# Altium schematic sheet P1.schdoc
size 660 x 381 mm; Symbol: Drawing-Symbol_A4; @Project Name: Assisant vocal; @Page Count: 1; @Update Date: 2026-05-30; @Create Date: 2026-02-09; @Schematic Name: Cerveau; @Page No: 1; @Page Name: P1; Company: EasyEDA.com; Version: V1.0; Page Size: A4; @Create Time: 11:08:47; @Update Time: 16:26:07; Border: 1; Width: 2600; Height: 1500; Region Start: 1; X Region Count: 6; Y Region Count: 4; Blade Width: 10; Title Block Position: 3; @Board Name: Cerveau; Device: Drawing-Symbol_A4
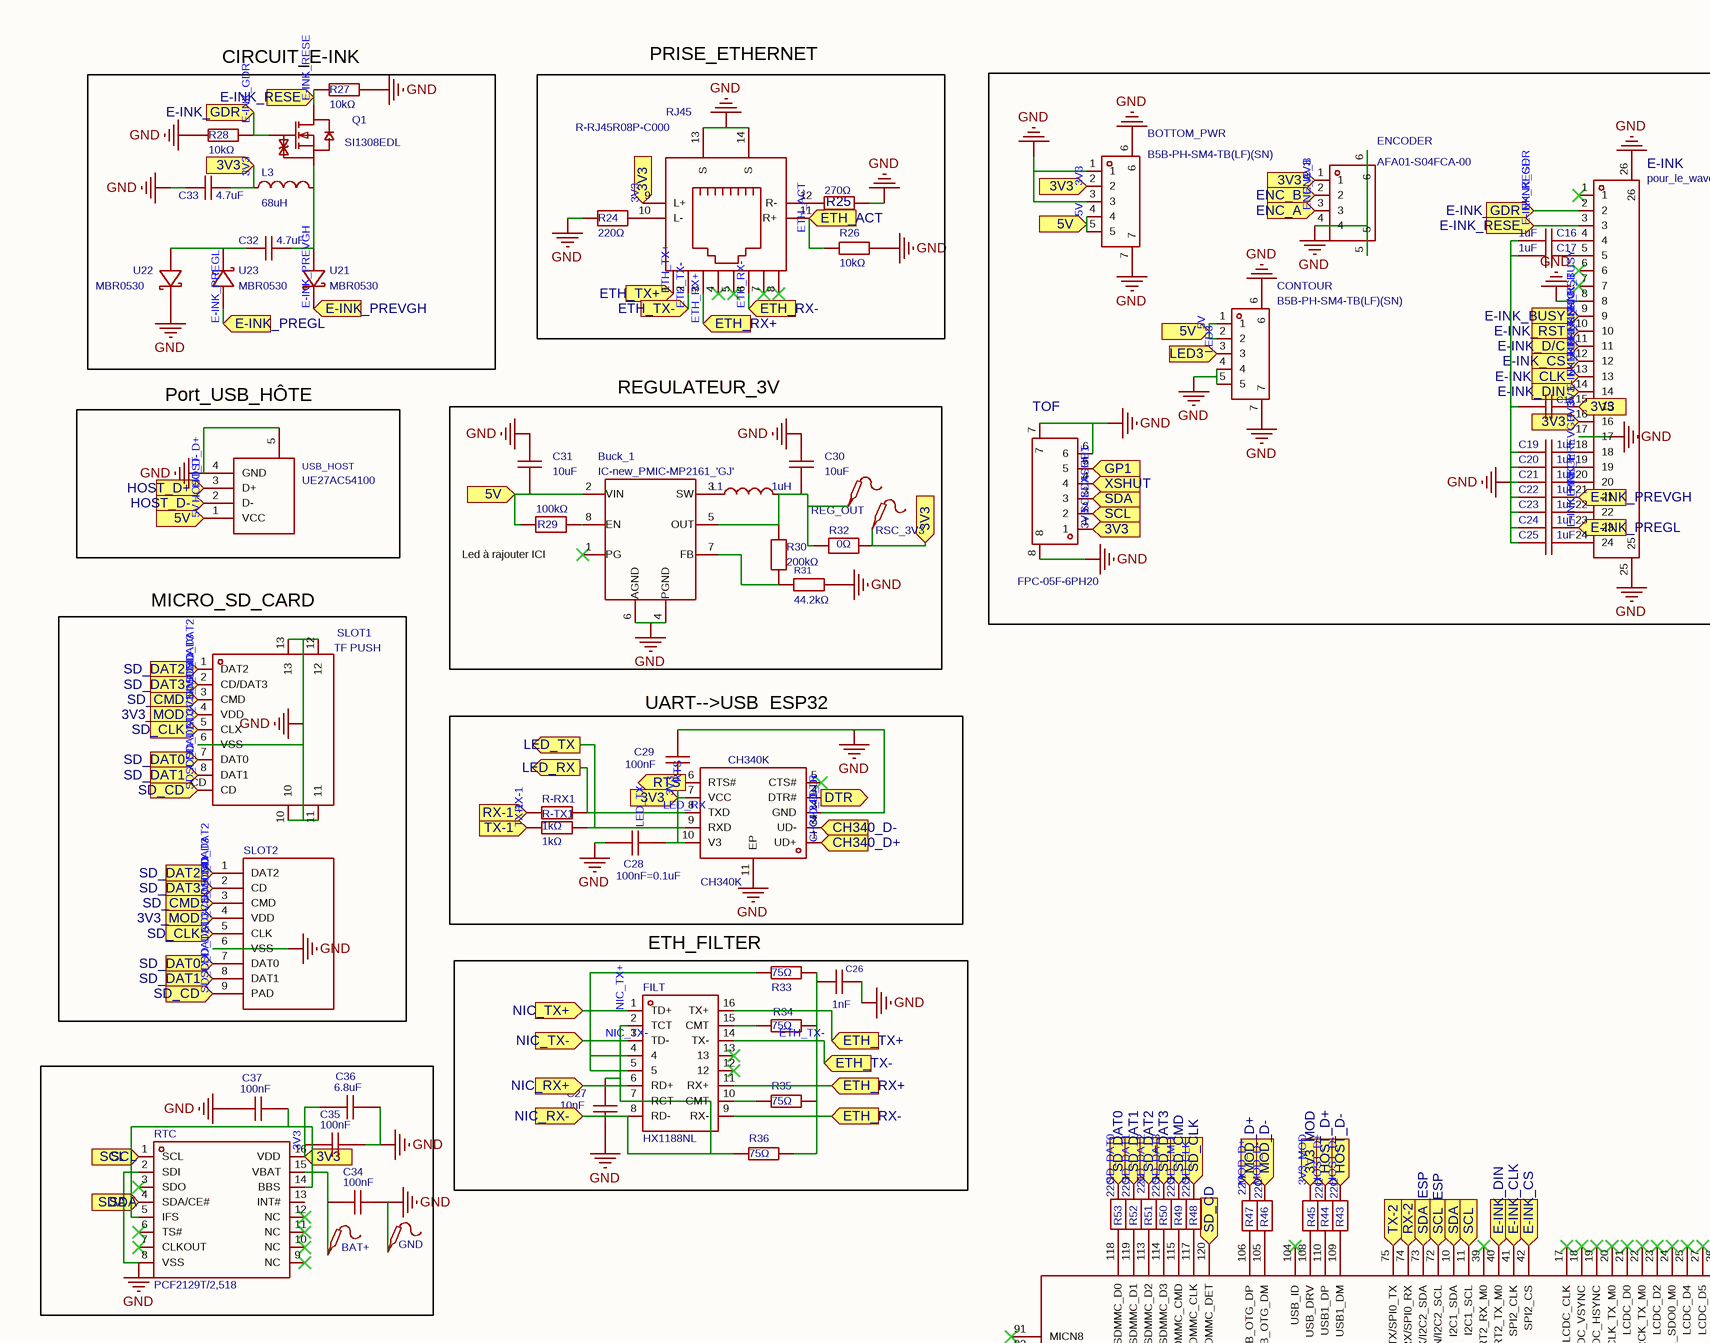
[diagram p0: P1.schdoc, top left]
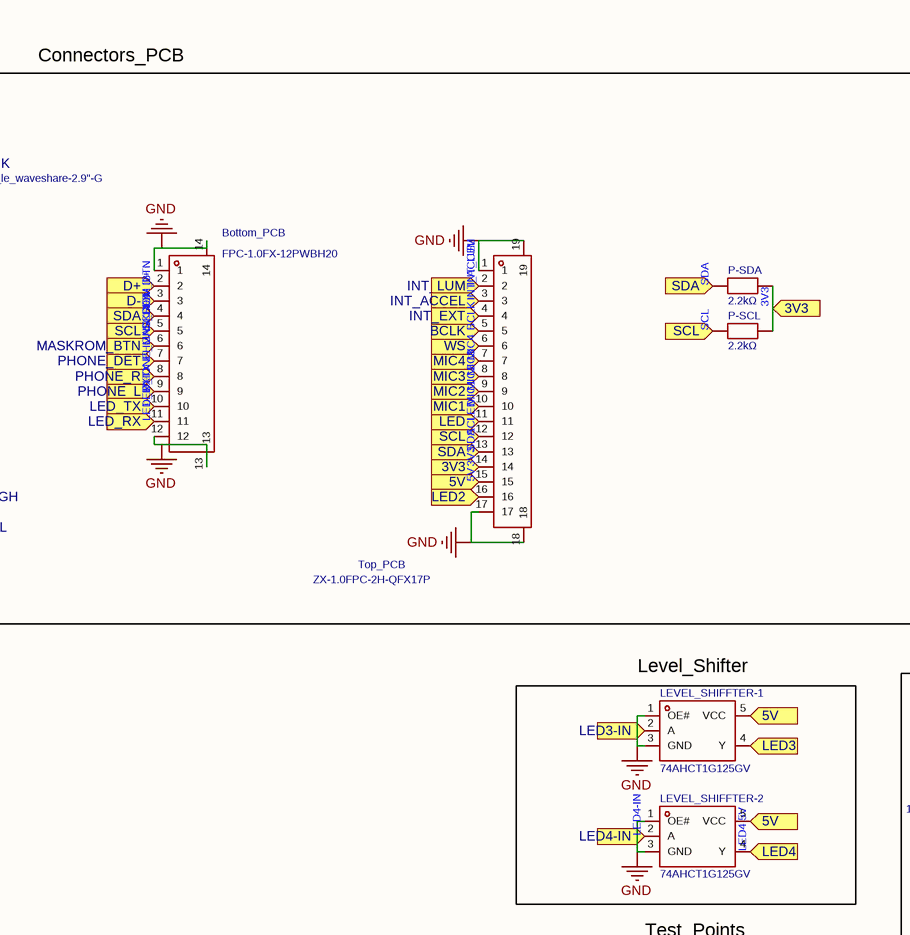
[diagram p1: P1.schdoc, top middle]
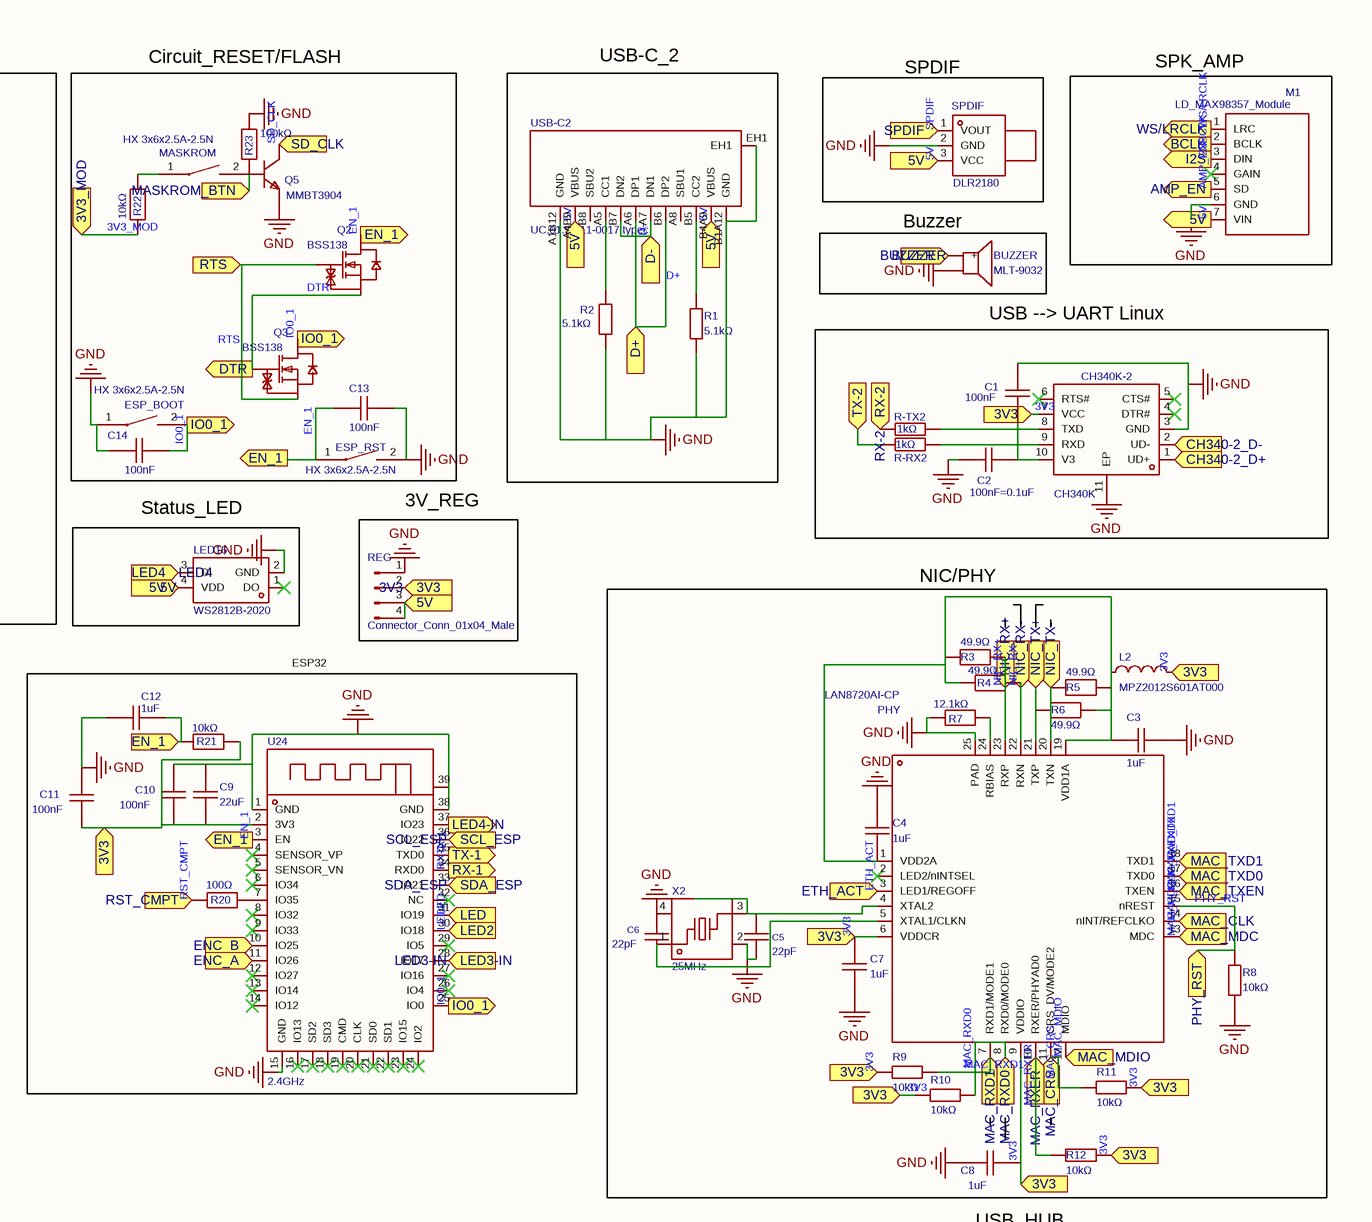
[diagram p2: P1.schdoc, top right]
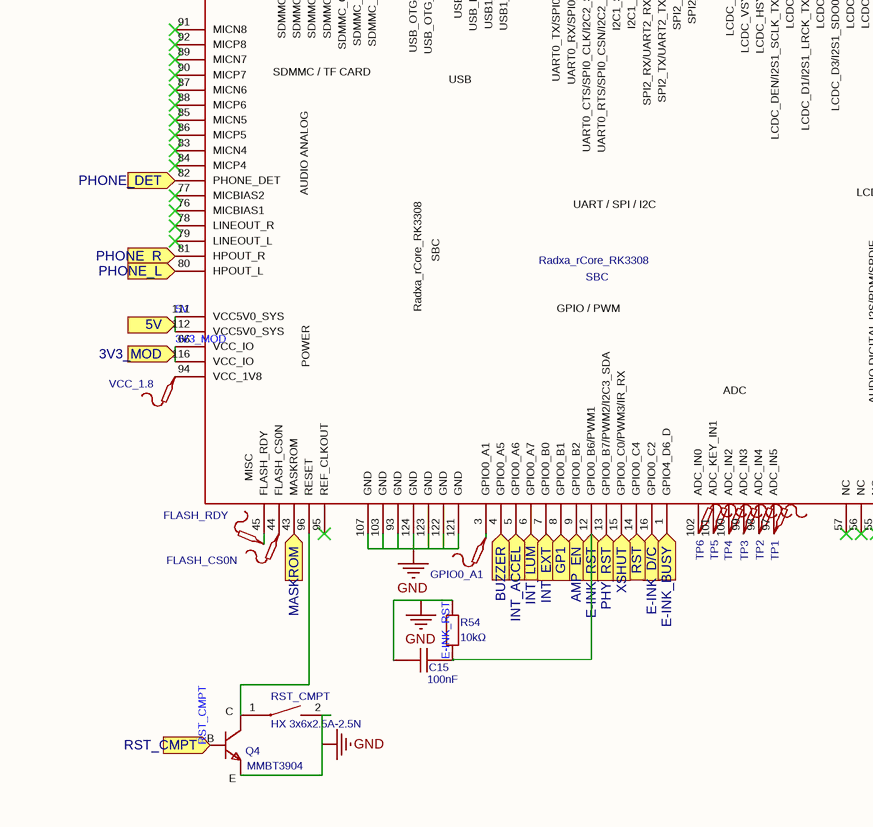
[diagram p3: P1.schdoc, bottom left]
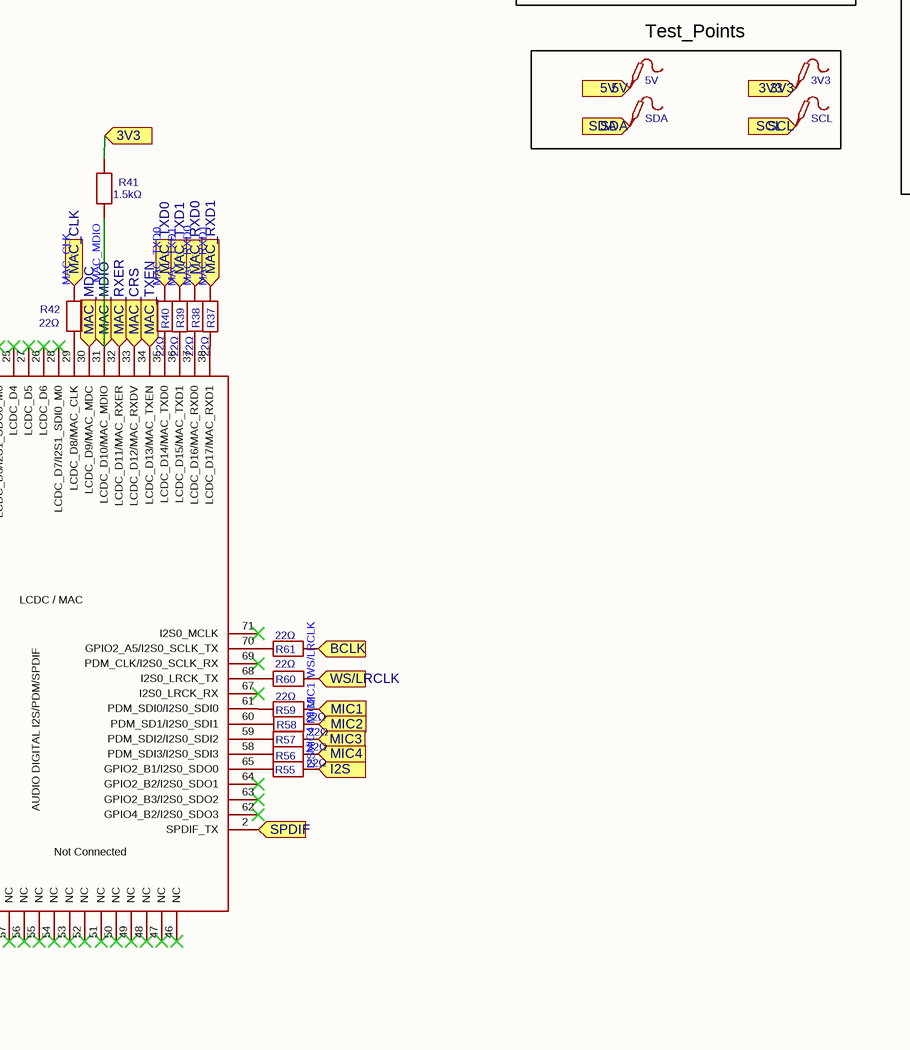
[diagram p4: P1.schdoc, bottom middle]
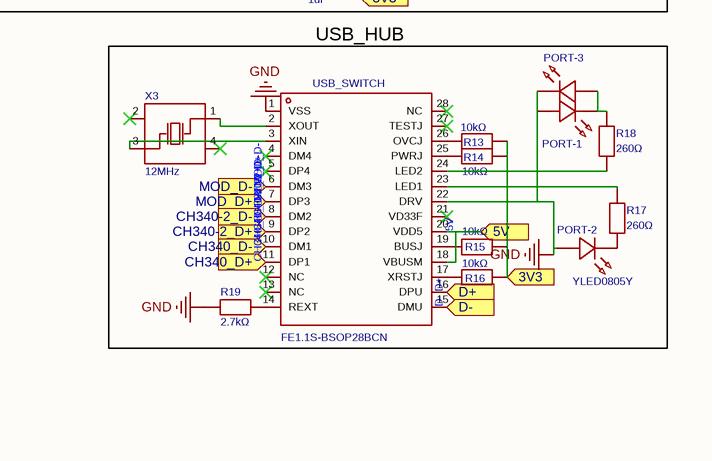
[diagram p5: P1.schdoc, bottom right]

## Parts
3V3  (no value)  [Test-Point-0.5mm]
5V  (no value)  [Test-Point-0.5mm]
BAT+  (no value)  [Test-Point-0.5mm]
Bottom_PCB  FPC-1.0FX-12PWBH20  [FPC-SMD_12P-P1.00_XUNPU_FPC-1.0FX-12PWBH20]
BOTTOM_PWR  B5B-PH-SM4-TB(LF)(SN)  [CONN-SMD_5P-P2.00_B6B-PH-SM4-TB-LF-SN]
Buck_1  IC-new_PMIC-MP2161_'GJ'  [TSOT23-8]
BUZZER  MLT-9032  [BUZ-SMD_MLT-9032]
C1  100nF  [C0603]
C2  100nF=0.1uF  [C0603]
C3  1uF  [C0603]
C4  1uF  [C0603]
C5  22pF  [C0603]
C6  22pF  [C0603]
C7  1uF  [C0603]
C8  1uF  [C0603]
C9  22uF  [C0603]
C10  100nF  [C0603]
C11  100nF  [C0603]
C12  1uF  [C0603]
C13  100nF  [C0603]
C14  100nF  [C0603]
C15  100nF  [C0603]
C16  1uF  [C0603]
C17  1uF  [C0603]
C18  CC0603KRX7R6BB104  [C0603]  (value not drawn)
C19  1uF  [C0603]
C20  1uF  [C0603]
C21  1uF  [C0603]
C22  1uF  [C0603]
C23  1uF  [C0603]
C24  1uF  [C0603]
C25  1uF  [C0603]
C26  1nF  [C0603]
C27  10nF  [C0603]
C28  100nF=0.1uF  [C0603]
C29  100nF  [C0603]
C30  10uF  [C0603]
C31  10uF  [C0603]
C32  4.7uF  [C0805]
C33  4.7uF  [C0805]
C34  100nF  [C0603]
C35  100nF  [C0603]
C36  6.8uF  [C0603]
C37  100nF  [C0603]
CH340K  CH340K  [ESOP-10_L4.9-W3.9-P1.00-LS6.2-BL-EP]
CH340K-2  CH340K  [ESOP-10_L4.9-W3.9-P1.00-LS6.2-BL-EP]
CONTOUR  B5B-PH-SM4-TB(LF)(SN)  [CONN-SMD_5P-P2.00_B6B-PH-SM4-TB-LF-SN]
E-INK  pour_le_waveshare-2.9"-G  [FPC-SMD_24P-P0.50_FPC-05F-24PH20]
ENCODER  AFA01-S04FCA-00  [FPC-SMD_4P-P1.00_JS_AFA01-S04FCA-00]
ESP_BOOT  HX 3x6x2.5A-2.5N  [SW-SMD_HX-TS-1101-C-W]
ESP_RST  HX 3x6x2.5A-2.5N  [SW-SMD_HX-TS-1101-C-W]
FILT  HX1188NL  [XFMR-SMD_16P-L12.7-W7.1-P1.27-LS9.4-BL]
FLASH_CS0N  (no value)  [Test-Point-0.5mm]
FLASH_RDY  (no value)  [Test-Point-0.5mm]
GND  (no value)  [Test-Point-0.5mm]
GPIO0_A1  (no value)  [Test-Point-0.5mm]
L1  1uH  [IND-SMD_L4.0-W4.0_ANR4012]
L2  MPZ2012S601AT000  [L0805]
L3  68uH  [IND-SMD_L7.1-W6.6_H5.0]
LED16  WS2812B-2020  [LED-SMD_4P-L2.0-W2.0-TL_WS2812B-2020]
LEVEL_SHIFFTER-1  74AHCT1G125GV  [SOT-23-5_L3.0-W1.7-P0.95-LS2.8-BL]
LEVEL_SHIFFTER-2  74AHCT1G125GV  [SOT-23-5_L3.0-W1.7-P0.95-LS2.8-BL]
M1  LD_MAX98357_Module  [LD:MAX98357_Module]
MASKROM  HX 3x6x2.5A-2.5N  [SW-SMD_HX-TS-1101-C-W]
P-SCL  2.2kΩ  [R0603]
P-SDA  2.2kΩ  [R0603]
PHY  LAN8720AI-CP  [QFN-24_L4.0-W4.0-P0.50-BL-EP2.6]
PORT-1  YLED0805Y  [LED0805-RD_YELLOW]  (value not drawn)
PORT-2  YLED0805Y  [LED0805-RD_YELLOW]
PORT-3  YLED0805Y  [LED0805-RD_YELLOW]  (value not drawn)
Q1  SI1308EDL  [SOT-323-3_L2.0-W1.3-P1.30-LS2.1-BR]
Q2  BSS138  [SOT-23-3_L3.0-W1.7-P0.95-LS2.9-BR]
Q3  BSS138  [SOT-23-3_L3.0-W1.7-P0.95-LS2.9-BR]
Q4  MMBT3904  [TSOT-23-3_L3.0-W1.6-P0.95-LS2.8-BR]
Q5  MMBT3904  [TSOT-23-3_L3.0-W1.6-P0.95-LS2.8-BR]
R1  5.1kΩ  [R0603_1]
R2  5.1kΩ  [R0603_1]
R3  49.9Ω  [R0603]
R4  49.9Ω  [R0603]
R5  49.9Ω  [R0603]
R6  49.9Ω  [R0603]
R7  12.1kΩ  [R0603]
R8  10kΩ  [R0603]
R9  10kΩ  [R0603]
R10  10kΩ  [R0603]
R11  10kΩ  [R0603]
R12  10kΩ  [R0603]
R13  10kΩ  [R0603]
R14  10kΩ  [R0603]
R15  10kΩ  [R0603]
R16  10kΩ  [R0603]
R17  260Ω  [R0805]
R18  260Ω  [R0805]
R19  2.7kΩ  [R0603]
R20  100Ω  [R0603]
R21  10kΩ  [R0603]
R22  10kΩ  [R0603]
R23  100kΩ  [R0603]
R24  220Ω  [R0603]
R25  270Ω  [R0603]
R26  10kΩ  [R0603]
R27  10kΩ  [R0603]
R28  10kΩ  [R0603]
R29  100kΩ  [R0603]
R30  200kΩ  [R0603]
R31  44.2kΩ  [R0603]
R32  0Ω  [R0402]
R33  75Ω  [R0603]
R34  75Ω  [R0603]
R35  75Ω  [R0603]
R36  75Ω  [R0603]
R37  22Ω  [R0603]
R38  22Ω  [R0603]
R39  22Ω  [R0603]
R40  22Ω  [R0603]
R41  1.5kΩ  [R0603]
R42  22Ω  [R0603]
R43  22Ω  [R0603]
R44  22Ω  [R0603]
R45  FRC0603J104 TS  [R0603]  (value not drawn)
R46  22Ω  [R0603]
R47  22Ω  [R0603]
R48  22Ω  [R0603]
R49  22Ω  [R0603]
R50  22Ω  [R0603]
R51  22Ω  [R0603]
R52  22Ω  [R0603]
R53  22Ω  [R0603]
R54  10kΩ  [R0603]
R55  22Ω  [R0603]
R56  22Ω  [R0603]
R57  22Ω  [R0603]
R58  22Ω  [R0603]
R59  22Ω  [R0603]
R60  22Ω  [R0603]
R61  22Ω  [R0603]
R-RX1  1kΩ  [R0603_1]
R-RX2  1kΩ  [R0603_1]
R-TX1  1kΩ  [R0603_1]
R-TX2  1kΩ  [R0603_1]
REG  Connector_Conn_01x04_Male  [Connector_PinHeader_2.54mm:PinHeader_1x04_P2.54mm_Vertical]
REG_OUT  (no value)  [Test-Point-0.5mm]
RJ45  R-RJ45R08P-C000  [RJ45-TH_R-RJ45R08P-C000]
RSC_3V3  (no value)  [Test-Point-0.5mm]
RST_CMPT  HX 3x6x2.5A-2.5N  [SW-SMD_HX-TS-1101-C-W]
RTC  PCF2129T/2,518  [SO-16_L10.3-W7.5-P1.27-LS10.3-BL]
SBC  Radxa_rCore_RK3308  [Radxa_rCore_RK3308-bon_1]
SCL  (no value)  [Test-Point-0.5mm]
SDA  (no value)  [Test-Point-0.5mm]
SLOT1  TF PUSH  [TF-SMD_TF-PUSH]
SLOT2  (no value)  [TF-SMD_TF-025]
SPDIF  DLR2180  [CONN-TH_DLR2180_1]
TOF  FPC-05F-6PH20  [FPC-SMD_6P-P0.50_XUNPU_FPC-05F-6PH20]
Top_PCB  ZX-1.0FPC-2H-QFX17P  [FPC-SMD_17P-P1.00_ZX-1.0FPC-2H-QFX17P]
TP1  (no value)  [Test-Point-0.5mm]
TP2  (no value)  [Test-Point-0.5mm]
TP3  (no value)  [Test-Point-0.5mm]
TP4  (no value)  [Test-Point-0.5mm]
TP5  (no value)  [Test-Point-0.5mm]
TP6  (no value)  [Test-Point-0.5mm]
U21  MBR0530  [SOD-123_L2.7-W1.6-LS3.7-RD-1]
U22  MBR0530  [SOD-123_L2.7-W1.6-LS3.7-RD-1]
U23  MBR0530  [SOD-123_L2.7-W1.6-LS3.7-RD-1]
U24  2.4GHz  [WIFIM-SMD_38P-L19.2-W18.0-P1.27]
USB-C2  UC.01.51-11-0017,typec  [TYPE-C-SMD_UC.01.51-11-0017]
USB_HOST  UE27AC54100  [USB-A-TH_UE27AC54100]
USB_SWITCH  FE1.1S-BSOP28BCN  [SSOP-28_L9.9-W3.9-P0.635-LS6.0-BL-1]
VCC_1.8  (no value)  [Test-Point-0.5mm]
X2  25MHz  [CRYSTAL-SMD_4P-L5.0-W3.2-BL]
X3  12MHz  [CRYSTAL-SMD_4P-L3.2-W2.5-BL]

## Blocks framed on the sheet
CIRCUIT_E-INK: C32 C33 L3 Q1 R27 R28 U21-U23
PRISE_ETHERNET: R24-R26 RJ45
Connectors_PCB: Bottom_PCB BOTTOM_PWR C16-C25 CONTOUR E-INK ENCODER P-SCL P-SDA TOF Top_PCB
Circuit_RESET/FLASH: C13 C14 ESP_BOOT ESP_RST MASKROM Q2 Q3 Q5 R22 R23
USB-C_2: R1 R2 USB-C2
SPDIF: SPDIF
SPK_AMP: M1
Buzzer: BUZZER
USB --> UART Linux: C1 C2 CH340K-2 R-RX2 R-TX2
Port_USB_HÔTE: USB_HOST
REGULATEUR_3V: Buck_1 C30 C31 L1 R29-R32 REG_OUT RSC_3V3
Status_LED: LED16
3V_REG: REG
MICRO_SD_CARD: SLOT1 SLOT2
NIC/PHY: C3-C8 L2 PHY R3-R12 X2
ESP32: C9-C12 R20 R21 U24
UART-->USB  ESP32: C28 C29 CH340K R-RX1 R-TX1
Level_Shifter: LEVEL_SHIFFTER-1 LEVEL_SHIFFTER-2
ETH_FILTER: C26 C27 FILT R33-R36
Test_Points: 3V3 5V SCL SDA
USB_HUB: PORT-1-PORT-3 R13-R19 USB_SWITCH X3

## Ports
3V3 (in), 3V3_MOD (in), 5V (in), 5V (out), AMP_EN (in), AMP_EN (out), BCLK (in), BCLK (out), BUZZER (in), CH340-2_D+ (in), CH340-2_D- (in), CH340_D+ (in), CH340_D- (in), D+ (in), D- (in), DTR (out), E-INK_BUSY (in), E-INK_CLK (in), E-INK_CS (in), E-INK_D/C (in), E-INK_DIN (in), E-INK_GDR (in), E-INK_PREGL (in), E-INK_PREVGH (in), E-INK_RESE (in), E-INK_RST (in), EN_1 (in), EN_1 (out), ENC_A (in), ENC_B (in), ETH_ACT (in), ETH_RX+ (in), ETH_RX- (in), ETH_TX+ (in), ETH_TX- (in), GP1 (in), HOST_D+ (in), HOST_D- (in), I2S (in), I2S (out), INT_ACCEL (in), INT_EXT (in), INT_LUM (in), IO0_1 (out), LED2 (in), LED3 (in), LED3-IN (in), LED4 (in), LED4-IN (in), LED4-IN (out), LED (in), LED_RX (in), LED_RX (out), LED_TX (in), LED_TX (out), MAC_CLK (in), MAC_CRS (in), MAC_MDC (in), MAC_MDIO (in), MAC_RXD0 (in), MAC_RXD1 (in), MAC_RXER (in), MAC_TXD0 (in), MAC_TXD1 (in), MAC_TXEN (in), MASKROM (in), MASKROM_BTN (in), MIC1 (in), MIC2 (in), MIC3 (in), MIC4 (in), MOD_D+ (in), MOD_D- (in), NIC_RX+ (in), NIC_RX- (in), NIC_TX+ (in), NIC_TX- (in), PHONE_DET (in), PHONE_L (in), PHONE_R (in), PHY_RST (in), RST (in), RST_CMPT (in), RTS (in), RTS (out), RX-1 (in), RX-1 (out), RX-2 (in), SCL (in), SCL_ESP (in), SD_CD (in), SD_CLK (in), SD_CMD (in), SD_DAT0 (in), SD_DAT1 (in), SD_DAT2 (in), SD_DAT3 (in), SDA (in), SDA_ESP (in), SPDIF (in), TX-1 (in), TX-1 (out), TX-2 (in), WS (in), WS/LRCLK (in), WS/LRCLK (out), XSHUT (in)

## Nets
GND: Bottom_PCB.1 Bottom_PCB.12 Bottom_PCB.13 Bottom_PCB.14 BOTTOM_PWR.1 BOTTOM_PWR.3 BOTTOM_PWR.6 BOTTOM_PWR.7 Buck_1.4(PGND) Buck_1.6(AGND) BUZZER.2 C1.1 C2.2 C3.2 C4.1 C5.1 C6.2 C7.2 C8.1 C9.2 C10.1 C11.2 C12.2 C13.2 C14.1 C15.1 C16.1 C17.1 C18.1 C19.2 C20.2 C21.2 C22.2 C23.2 C24.2 C25.2 C26.1 C27.1 C28.2 C29.1 C30.2 C31.2 C33.1 C34.2 C35.2 C36.1 C37.2 CH340K.3(GND) CH340K.11(EP) CH340K-2.3(GND) CH340K-2.11(EP) CONTOUR.4 CONTOUR.5 CONTOUR.6 CONTOUR.7 E-INK.8 E-INK.17 E-INK.25 E-INK.26 ENCODER.4 ENCODER.5 ENCODER.6 ESP_BOOT.1 ESP_RST.2 GND.1 LED16.2(GND) LEVEL_SHIFFTER-1.1(OE#) LEVEL_SHIFFTER-1.3(GND) LEVEL_SHIFFTER-2.1(OE#) LEVEL_SHIFFTER-2.3(GND) M1.6(GND) PHY.25(PAD) PORT-1.2(A) PORT-2.2(A) PORT-3.1(K) Q4.2(E) Q5.2(E) R1.1 R2.1 R7.1 R8.2 R19.1 R23.2 R24.1 R25.2 R26.2 R27.2 R28.1 R31.2 R54.1 REG.1(Pin_1) RJ45.13(S) RJ45.14(S) RST_CMPT.2 RTC.2(SDI) RTC.8(VSS) SBC.93(GND) SBC.103(GND) SBC.107(GND) SBC.121(GND) SBC.122(GND) SBC.123(GND) SBC.124(GND) SLOT1.6(VSS) SLOT1.10 SLOT1.11 SLOT1.12 SLOT1.13 SLOT2.6(VSS) SPDIF.2(GND) TOF.6 TOF.7 TOF.8 Top_PCB.1 Top_PCB.17 Top_PCB.18 Top_PCB.19 U22.1(K) U24.1(GND) U24.15(GND) U24.38(GND) U24.39(GND) USB-C2.A1B12(GND) USB-C2.B1A12(GND) USB-C2.EH1 USB_HOST.4(GND) USB_HOST.5(SHLD) USB_SWITCH.1(VSS) USB_SWITCH.22(DRV) X2.2(GND) X2.4(GND)
3V3: 3V3.1 BOTTOM_PWR.2 C7.1 C8.2 C9.1 C10.2 C11.1 C18.2 C28.1 C29.2 C33.2 C35.1 C36.2 CH340K.7(VCC) CH340K.10(V3) CH340K-2.7(VCC) E-INK.15 E-INK.16 ENCODER.1 L2.2 L3.1 P-SCL.2 P-SDA.2 PHY.6(VDDCR) PHY.9(VDDIO) R9.1 R10.1 R11.2 R12.2 R13.2 R14.2 R15.2 R16.2 R21.2 R32.2 R41.2 REG.2(Pin_2) RJ45.9(L+) RSC_3V3.1 RTC.16(VDD) TOF.1 Top_PCB.14 U24.2(3V3) ; port 3V3
3V3_MOD: R22.2 R45.2 SBC.66(VCC_IO) SBC.116(VCC_IO) SLOT1.4(VDD) SLOT2.4(VDD) ; port 3V3_MOD
5V: 5V.1 BOTTOM_PWR.4 BOTTOM_PWR.5 Buck_1.2(VIN) C31.1 CONTOUR.1 CONTOUR.2 LED16.4(VDD) LEVEL_SHIFFTER-1.5(VCC) LEVEL_SHIFFTER-2.5(VCC) M1.7(VIN) R29.1 REG.3(Pin_3) REG.4(Pin_4) SBC.111(VCC5V0_SYS) SBC.112(VCC5V0_SYS) SPDIF.3(VCC) Top_PCB.15 USB-C2.A4B9(VBUS) USB-C2.B4A9(VBUS) USB_HOST.1(VCC) USB_SWITCH.18(VBUSM) USB_SWITCH.20(VDD5) ; port 5V
AMP_EN: M1.5(SD) SBC.9(GPIO0_B2) ; port AMP_EN
BCLK: M1.2(BCLK) R61.2 Top_PCB.5 ; port BCLK
BUZZER: BUZZER.1(+) SBC.4(GPIO0_A5) ; port BUZZER
CH340-2_D+: CH340K-2.1(UD+) USB_SWITCH.9(DP2) ; port CH340-2_D+
CH340-2_D-: CH340K-2.2(UD-) USB_SWITCH.8(DM2) ; port CH340-2_D-
CH340_D+: CH340K.1(UD+) USB_SWITCH.11(DP1) ; port CH340_D+
CH340_D-: CH340K.2(UD-) USB_SWITCH.10(DM1) ; port CH340_D-
D+: Bottom_PCB.2 USB-C2.A6(DP1) USB-C2.B6(DP2) USB_SWITCH.16(DPU) ; port D+
D-: Bottom_PCB.3 USB-C2.A7(DN1) USB-C2.B7(DN2) USB_SWITCH.15(DMU) ; port D-
DTR: CH340K.4(DTR#) Q2.2(S) Q3.1(G) ; port DTR
E-INK_BUSY: E-INK.9 SBC.1(GPIO4_D6_D) ; port E-INK_BUSY
E-INK_CLK: E-INK.13 SBC.41(SPI2_CLK) ; port E-INK_CLK
E-INK_CS: E-INK.12 SBC.42(SPI2_CS) ; port E-INK_CS
E-INK_D/C: E-INK.11 SBC.16(GPIO0_C2) ; port E-INK_D/C
E-INK_DIN: E-INK.14 SBC.40(SPI2_TX/UART2_TX_M0) ; port E-INK_DIN
E-INK_GDR: E-INK.2 Q1.1(G) R28.2 ; port E-INK_GDR
E-INK_PREGL: C24.1 E-INK.23 U23.2(A) ; port E-INK_PREGL
E-INK_PREVGH: C22.1 E-INK.21 U21.1(K) ; port E-INK_PREVGH
E-INK_RESE: E-INK.3 Q1.3(D) R27.1 ; port E-INK_RESE
E-INK_RST: C15.2 E-INK.10 R54.2 SBC.12(GPIO0_B6/PWM1) ; port E-INK_RST
EN_1: C12.1 C13.1 ESP_RST.1 Q2.3(D) R21.1 U24.3(EN) ; port EN_1
ENC_A: ENCODER.3 U24.11(IO26) ; port ENC_A
ENC_B: ENCODER.2 U24.10(IO25) ; port ENC_B
ETH_ACT: PHY.3(LED1/REGOFF) R26.1 RJ45.11(R+) ; port ETH_ACT
ETH_RX+: FILT.11(RX+) RJ45.3 ; port ETH_RX+
ETH_RX-: FILT.9(RX-) RJ45.6 ; port ETH_RX-
ETH_TX+: FILT.16(TX+) RJ45.1 ; port ETH_TX+
ETH_TX-: FILT.14(TX-) RJ45.2 ; port ETH_TX-
GP1: SBC.8(GPIO0_B1) TOF.5 ; port GP1
HOST_D+: R44.2 USB_HOST.3(D+) ; port HOST_D+
HOST_D-: R43.2 USB_HOST.2(D-) ; port HOST_D-
I2S: M1.3(DIN) R55.2 ; port I2S
INT_ACCEL: SBC.5(GPIO0_A6) Top_PCB.3 ; port INT_ACCEL
INT_EXT: SBC.7(GPIO0_B0) Top_PCB.4 ; port INT_EXT
INT_LUM: SBC.6(GPIO0_A7) Top_PCB.2 ; port INT_LUM
IO0_1: C14.2 ESP_BOOT.2 Q3.3(D) U24.25(IO0) ; port IO0_1
LED: Top_PCB.11 U24.31(IO19) ; port LED
LED2: Top_PCB.16 U24.30(IO18) ; port LED2
LED3: CONTOUR.3 LEVEL_SHIFFTER-1.4(Y) ; port LED3
LED3-IN: LEVEL_SHIFFTER-1.2(A) U24.28(IO17) ; port LED3-IN
LED4: LED16.3(DI) LEVEL_SHIFFTER-2.4(Y) ; port LED4
LED4-IN: LEVEL_SHIFFTER-2.2(A) U24.37(IO23) ; port LED4-IN
LED_RX: Bottom_PCB.11 CH340K.8(TXD) R-RX1.1 ; port LED_RX
LED_TX: Bottom_PCB.10 CH340K.9(RXD) R-TX1.1 ; port LED_TX
MAC_CLK: PHY.14(nINT/REFCLKO) R42.2 ; port MAC_CLK
MAC_CRS: PHY.11(CRS_DV/MODE2) R11.1 SBC.33(LCDC_D12/MAC_RXDV) ; port MAC_CRS
MAC_MDC: PHY.13(MDC) SBC.30(LCDC_D9/MAC_MDC) ; port MAC_MDC
MAC_MDIO: PHY.12(MDIO) R41.1 SBC.31(LCDC_D10/MAC_MDIO) ; port MAC_MDIO
MAC_RXD0: PHY.8(RXD0/MODE0) R10.2 R38.2 ; port MAC_RXD0
MAC_RXD1: PHY.7(RXD1/MODE1) R9.2 R37.2 ; port MAC_RXD1
MAC_RXER: PHY.10(RXER/PHYAD0) R12.1 SBC.32(LCDC_D11/MAC_RXER) ; port MAC_RXER
MAC_TXD0: PHY.17(TXD0) R40.2 ; port MAC_TXD0
MAC_TXD1: PHY.18(TXD1) R39.2 ; port MAC_TXD1
MAC_TXEN: PHY.16(TXEN) SBC.34(LCDC_D13/MAC_TXEN) ; port MAC_TXEN
MASKROM: SBC.43(MASKROM) ; port MASKROM
MASKROM_BTN: Bottom_PCB.6 MASKROM.2 Q5.1(B) R23.1 ; port MASKROM_BTN
MIC1: R59.2 Top_PCB.10 ; port MIC1
MIC2: R58.2 Top_PCB.9 ; port MIC2
MIC3: R57.2 Top_PCB.8 ; port MIC3
MIC4: R56.2 Top_PCB.7 ; port MIC4
MOD_D+: R47.2 USB_SWITCH.7(DP3) ; port MOD_D+
MOD_D-: R46.2 USB_SWITCH.6(DM3) ; port MOD_D-
NIC_RX+: FILT.6(RD+) PHY.23(RXP) R3.2 ; port NIC_RX+
NIC_RX-: C27.2 FILT.2(TCT) FILT.7(RCT) FILT.8(RD-) PHY.22(RXN) R4.2 R36.1 ; port NIC_RX-
NIC_TX+: FILT.1(TD+) PHY.21(TXP) R6.1 ; port NIC_TX+
NIC_TX-: FILT.3(TD-) PHY.20(TXN) R5.1 ; port NIC_TX-
PHONE_DET: Bottom_PCB.7 SBC.82(PHONE_DET) ; port PHONE_DET
PHONE_L: Bottom_PCB.9 SBC.80(HPOUT_L) ; port PHONE_L
PHONE_R: Bottom_PCB.8 SBC.81(HPOUT_R) ; port PHONE_R
PHY_RST: PHY.15(nREST) R8.1 SBC.13(GPIO0_B7/PWM2/I2C3_SDA) ; port PHY_RST
RST: SBC.14(GPIO0_C4) ; port RST
RST_CMPT: Q4.1(B) R20.1 ; port RST_CMPT
RTS: CH340K.6(RTS#) Q2.1(G) Q3.2(S) ; port RTS
RX-1: R-RX1.2 U24.34(RXD0) ; port RX-1
RX-2: R-RX2.2 SBC.74(UART0_RX/SPI0_RX) ; port RX-2
SCL: Bottom_PCB.5 P-SCL.1 RTC.1(SCL) SBC.11(I2C1_SCL) SCL.1 TOF.2 Top_PCB.12 ; port SCL
SCL_ESP: SBC.72(UART0_RTS/SPI0_CSN/I2C2_SCL) U24.36(IO22) ; port SCL_ESP
SD_CD: SBC.120(SDMMC_DET) SLOT1.CD SLOT2.9(PAD) ; port SD_CD
SD_CLK: Q5.3(C) R48.2 SLOT1.5(CLX) SLOT2.5(CLK) ; port SD_CLK
SD_CMD: R49.2 SLOT1.3(CMD) SLOT2.3(CMD) ; port SD_CMD
SD_DAT0: R53.2 SLOT1.7(DAT0) SLOT2.7(DAT0) ; port SD_DAT0
SD_DAT1: R52.2 SLOT1.8(DAT1) SLOT2.8(DAT1) ; port SD_DAT1
SD_DAT2: R51.2 SLOT1.1(DAT2) SLOT2.1(DAT2) ; port SD_DAT2
SD_DAT3: R50.2 SLOT1.2(CD/DAT3) SLOT2.2(CD) ; port SD_DAT3
SDA: Bottom_PCB.4 P-SDA.1 RTC.4(SDA/CE#) SBC.10(I2C1_SDA) SDA.1 TOF.3 Top_PCB.13 ; port SDA
SDA_ESP: SBC.73(UART0_CTS/SPI0_CLK/I2C2_SDA) U24.33(IO21) ; port SDA_ESP
SPDIF: SBC.2(SPDIF_TX) SPDIF.1(VOUT) ; port SPDIF
TX-1: R-TX1.2 U24.35(TXD0) ; port TX-1
TX-2: R-TX2.2 SBC.75(UART0_TX/SPI0_TX) ; port TX-2
WS: Top_PCB.6 ; port WS
WS/LRCLK: M1.1(LRC) R60.2 ; port WS/LRCLK
XSHUT: SBC.15(GPIO0_C0/PWM3/IR_RX) TOF.4 ; port XSHUT
NetBAT+_1: BAT+.1 C34.1 RTC.15(VBAT)
NetBuck_1_3: Buck_1.3(SW) L1.1
NetBuck_1_5: Buck_1.5(OUT) C30.1 L1.2 R30.2 R32.1 REG_OUT.1
NetBuck_1_7: Buck_1.7(FB) R30.1 R31.1
NetBuck_1_8: Buck_1.8(EN) R29.2
NetC1_2: C1.2 C2.1 CH340K-2.10(V3)
NetC3_1: C3.1 C4.2 L2.1 PHY.1(VDD2A) PHY.19(VDD1A) R3.1 R4.1 R5.2 R6.2
NetC5_2: C5.2 PHY.4(XTAL2) X2.3
NetC6_1: C6.1 PHY.5(XTAL1/CLKN) X2.1
NetC16_2: C16.2 E-INK.4
NetC17_2: C17.2 E-INK.5
NetC19_1: C19.1 E-INK.18
NetC20_1: C20.1 E-INK.19
NetC21_1: C21.1 E-INK.20
NetC23_1: C23.1 E-INK.22
NetC25_1: C25.1 E-INK.24
NetC26_2: C26.2 R33.2 R34.2 R35.2 R36.2
NetC32_1: C32.1 U22.2(A) U23.1(K)
NetC32_2: C32.2 L3.2 Q1.2(S) U21.2(A)
NetC37_1: C37.1 RTC.5(IFS) RTC.14(BBS)
NetCH340K-2_8: CH340K-2.8(TXD) R-RX2.1
NetCH340K-2_9: CH340K-2.9(RXD) R-TX2.1
NetFILT_4: FILT.4 FILT.5 R33.1
NetFILT_10: FILT.10(CMT) R35.1
NetFILT_15: FILT.15(CMT) R34.1
NetFLASH_CS0N_1: FLASH_CS0N.1 SBC.44(FLASH_CS0N)
NetFLASH_RDY_1: FLASH_RDY.1 SBC.45(FLASH_RDY)
NetGPIO0_A1_1: GPIO0_A1.1 SBC.3(GPIO0_A1)
NetMASKROM_1: MASKROM.1 R22.1
NetPHY_24: PHY.24(RBIAS) R7.2
NetPORT-1_1: PORT-1.1(K) PORT-3.2(A) R18.2
NetPORT-2_1: PORT-2.1(K) R17.1
NetQ4_3: Q4.3(C) RST_CMPT.1 SBC.96(RESET)
NetR1_2: R1.2 USB-C2.B5(CC2)
NetR2_2: R2.2 USB-C2.A5(CC1)
NetR13_1: R13.1 USB_SWITCH.26(OVCJ)
NetR14_1: R14.1 USB_SWITCH.25(PWRJ)
NetR15_1: R15.1 USB_SWITCH.19(BUSJ)
NetR16_1: R16.1 USB_SWITCH.17(XRSTJ)
NetR17_2: R17.2 USB_SWITCH.23(LED1)
NetR18_1: R18.1 USB_SWITCH.24(LED2)
NetR19_2: R19.2 USB_SWITCH.14(REXT)
NetR20_2: R20.2 U24.7(IO35)
NetR24_2: R24.2 RJ45.10(L-)
NetR25_1: R25.1 RJ45.12(R-)
NetR37_1: R37.1 SBC.38(LCDC_D17/MAC_RXD1)
NetR38_1: R38.1 SBC.37(LCDC_D16/MAC_RXD0)
NetR39_1: R39.1 SBC.36(LCDC_D15/MAC_TXD1)
NetR40_1: R40.1 SBC.35(LCDC_D14/MAC_TXD0)
NetR42_1: R42.1 SBC.29(LCDC_D8/MAC_CLK)
NetR43_1: R43.1 SBC.109(USB1_DM)
NetR44_1: R44.1 SBC.110(USB1_DP)
NetR45_1: R45.1 SBC.108(USB_DRV)
NetR46_1: R46.1 SBC.105(USB_OTG_DM)
NetR47_1: R47.1 SBC.106(USB_OTG_DP)
NetR48_1: R48.1 SBC.117(SDMMC_CLK)
NetR49_1: R49.1 SBC.115(SDMMC_CMD)
NetR50_1: R50.1 SBC.114(SDMMC_D3)
NetR51_1: R51.1 SBC.113(SDMMC_D2)
NetR52_1: R52.1 SBC.119(SDMMC_D1)
NetR53_1: R53.1 SBC.118(SDMMC_D0)
NetR55_1: R55.1 SBC.65(GPIO2_B1/I2S0_SDO0)
NetR56_1: R56.1 SBC.58(PDM_SDI3/I2S0_SDI3)
NetR57_1: R57.1 SBC.59(PDM_SDI2/I2S0_SDI2)
NetR58_1: R58.1 SBC.60(PDM_SD1/I2S0_SDI1)
NetR59_1: R59.1 SBC.61(PDM_SDI0/I2S0_SDI0)
NetR60_1: R60.1 SBC.68(I2S0_LRCK_TX)
NetR61_1: R61.1 SBC.70(GPIO2_A5/I2S0_SCLK_TX)
NetSBC_94: SBC.94(VCC_1V8) VCC_1.8.1
NetSBC_97: SBC.97(ADC_IN5) TP1.1
NetSBC_98: SBC.98(ADC_IN4) TP2.1
NetSBC_99: SBC.99(ADC_IN3) TP3.1
NetSBC_100: SBC.100(ADC_IN2) TP4.1
NetSBC_101: SBC.101(ADC_KEY_IN1) TP5.1
NetSBC_102: SBC.102(ADC_IN0) TP6.1
NetUSB_SWITCH_2: USB_SWITCH.2(XOUT) X3.1(OSC1)
NetUSB_SWITCH_3: USB_SWITCH.3(XIN) X3.3(OSC2)

Not connected (* = marked no-connect by the designer): Buck_1 1(PG)*; CH340K 5(CTS#)*; CH340K-2 4(DTR#)* 5(CTS#)* 6(RTS#)*; E-INK 1* 6* 7*; FILT 12* 13*; LED16 1(DO)*; M1 4(GAIN)*; PHY 2(LED2/nINTSEL)*; RJ45 4* 5* 7* 8*; RTC 3(SDO)* 6(TS#)* 7(CLKOUT)* 9(NC)* 10(NC)* 11(NC)* 12(NC)* 13(INT#); SBC 17(LCDC_CLK)* 18(LCDC_VSYNC)* 19(LCDC_HSYNC)* 20(LCDC_DEN/I2S1_SCLK_TX_M0)* 21(LCDC_D0)* 22(LCDC_D1/I2S1_LRCK_TX_M0)* 23(LCDC_D2)* 24(LCDC_D3/I2S1_SDO0_M0)* 25(LCDC_D4)* 26(LCDC_D6)* 27(LCDC_D5)* 28(LCDC_D7/I2S1_SDI0_M0)* 39(SPI2_RX/UART2_RX_M0)* 46(NC)* 47(NC)* 48(NC)* 49(NC)* 50(NC)* 51(NC)* 52(NC)* 53(NC)* 54(NC)* 55(NC)* 56(NC)* 57(NC)* 62(GPIO4_B2/I2S0_SDO3)* 63(GPIO2_B3/I2S0_SDO2)* 64(GPIO2_B2/I2S0_SDO1)* 67(I2S0_LRCK_RX)* 69(PDM_CLK/I2S0_SCLK_RX)* 71(I2S0_MCLK)* 76(MICBIAS1)* 77(MICBIAS2)* 78(LINEOUT_R)* 79(LINEOUT_L)* 83(MICN4)* 84(MICP4)* 85(MICN5)* 86(MICP5)* 87(MICN6)* 88(MICP6)* 89(MICN7)* 90(MICP7)* 91(MICN8)* 92(MICP8)* 95(REF_CLKOUT)* 104(USB_ID)*; U24 4(SENSOR_VP)* 5(SENSOR_VN)* 6(IO34)* 8(IO32)* 9(IO33)* 12(IO27)* 13(IO14)* 14(IO12)* 16(IO13)* 17(SD2)* 18(SD3)* 19(CMD)* 20(CLK)* 21(SD0)* 22(SD1)* 23(IO15)* 24(IO2)* 26(IO4)* 27(IO16)* 29(IO5)* 32(NC)*; USB-C2 A8(SBU1) B8(SBU2); USB_SWITCH 4(DM4)* 5(DP4)* 12(NC)* 13(NC)* 21(VD33F)* 27(TESTJ)* 28(NC)*; X3 2(GND)* 4(GND)*

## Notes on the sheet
- Led à rajouter ICI
- (near Q4) B
- (near Q4) C
- (near Q4) E

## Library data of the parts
3V3 5V BAT+ FLASH_CS0N FLASH_RDY GND GPIO0_A1 REG_OUT RSC_3V3 SCL SDA TP1-TP6 VCC_1.8 = Test-Point: Test Point 测试点; AddInBom: yes
Bottom_PCB = FPC-1.0FX-12PWBH20: Locking Feature:Hinged Lid Contact Type:Surface Mount Number of Contacts:12P Pitch:1mm Mounting Type:Bottom Contact FFC, FCB Thickness:0.3mm FFC, FCB Thickness:0.3mm Height Above Board:2mm Contact Material:Phosphor Bronze Contact Plating:Tin Operating Tem; Manufacturer: XUNPU(讯普); AddInBom: yes; ModelId: 695df043a7de448bbae1c867db17c273; ModelTransform: 665.7467,242.1255,0,0,0,0,0.003,-68.386,0; Number of Contacts: 12P; Pitch: 1mm; FFC, FCB Thickness: 0.3mm; Rated Voltage (Max): 50V; Current Rating (Max): 500mA
BOTTOM_PWR CONTOUR = B5B-PH-SM4-TB(LF)(SN): Pins Structure:1x5P Pitch:2mm Mounting Type:Surface Mount,Vertical Reference Series:PH Number of Pins:5P Number of Rows:1 Number of PINs Per Row:5 Row Spacing:- Current Rating:2A Contact Material:Copper Alloy Contact Plating:Tin Operating Temperature:-25℃; Manufacturer: JST; AddInBom: yes; ModelId: 42661aa5dd484b92a752559c239d11dd; ModelTransform: 551.18,295.275,0,0,0,0,0,3.425,0; Pins Structure: 1x5P; Pitch: 2mm; Reference Series: PH; Number of PINs Per Row: 5; Current Rating: 2A; Voltage Rating: 100V; Plastic Material: PA; Flame Retardant Rating: UL94V-0; Supplementary Features: Auxiliary Solder Pin; Z-Height of the Board: 6.6mm; X-Length of Bottom Edge on Board (Spacing Line): 13.95mm; Y-Width of Bottom Edge on Board: 7mm
Buck_1 = IC-new_PMIC-MP2161_'GJ': AddInBom: yes; SymbolName: IC-new_PMIC-MP2161_&apos;GJ&apos;
BUZZER = MLT-9032: Manufacturer: 华能; AddInBom: yes; ModelId: 971d4ff6e0684907b414eeb9ddc11270; ModelTransform: 413.385,413.385,0,0,0,0,0,-29.528,0
C1 C2 C28 C29 = CC0603KRX7R9BB104: Capacitance:100nF Tolerance:±10% Tolerance:±10% Voltage Rating:50V Temperature Coefficient:X7R; Manufacturer: YAGEO(国巨); AddInBom: yes; ModelId: 624118aa3cc7497086c383c2d72e0852; ModelName: C0603_L1.6-W0.8-H0.8; ModelTransform: 62.992,31.496,0,0,0,0,0,0,0; Tolerance: ±10%; Voltage Rating: 50V; Temperature Coefficient: X7R
C3 C4 C7 C8 C19-C25 = CL10B105KB8NQNC: Capacitance:1uF Tolerance:±10% Tolerance:±10% Voltage Rating:50V Temperature Coefficient:X7R; Manufacturer: SAMSUNG(三星); AddInBom: yes; ModelId: 624118aa3cc7497086c383c2d72e0852; ModelName: C0603_L1.6-W0.8-H0.8; ModelTransform: 62.992,31.496,0,0,0,0,0,0,0; Tolerance: ±10%; Voltage Rating: 50V; Temperature Coefficient: X7R
C5 C6 = CC0603JRNPO9BN220: Capacitance:22pF Tolerance:±5% Tolerance:±5% Voltage Rating:50V Temperature Coefficient:NP0; Manufacturer: YAGEO(国巨); AddInBom: yes; ModelId: 624118aa3cc7497086c383c2d72e0852; ModelName: C0603_L1.6-W0.8-H0.8; ModelTransform: 62.992,31.496,0,0,0,0,0,0,0; Tolerance: ±5%; Voltage Rating: 50V; Temperature Coefficient: NP0
C9 = CL10A226MQ8NRNC: Capacitance:22uF Tolerance:±20% Tolerance:±20% Voltage Rating:6.3V Temperature Coefficient:X5R; Manufacturer: SAMSUNG(三星); AddInBom: yes; ModelId: 624118aa3cc7497086c383c2d72e0852; ModelName: C0603_L1.6-W0.8-H0.8; ModelTransform: 62.992,31.496,0,0,0,0,0,0,0; Tolerance: ±20%; Voltage Rating: 6.3V; Temperature Coefficient: X5R
C10 C11 C13 C14 = CGA0603X7R104K500JT: Capacitance:100nF Tolerance:±10% Tolerance:±10% Voltage Rating:50V Temperature Coefficient:X7R; Manufacturer: HRE(芯声); AddInBom: yes; ModelId: 624118aa3cc7497086c383c2d72e0852; ModelName: C0603_L1.6-W0.8-H0.8; ModelTransform: 62.992,31.496,0,0,0,0,0,0,0; Tolerance: ±10%; Voltage Rating: 50V; Temperature Coefficient: X7R
C12 = CGA0603X5R105K500JT: Capacitance:1uF Tolerance:±10% Tolerance:±10% Voltage Rating:50V Temperature Coefficient:X5R; Manufacturer: HRE(芯声); AddInBom: yes; ModelId: 624118aa3cc7497086c383c2d72e0852; ModelName: C0603_L1.6-W0.8-H0.8; ModelTransform: 62.992,31.496,0,0,0,0,0,0,0; Tolerance: ±10%; Voltage Rating: 50V; Temperature Coefficient: X5R
C15 = TCC0603X7R104K500CT: Capacitance:100nF Tolerance:±10% Tolerance:±10% Voltage Rating:50V Temperature Coefficient:X7R; Manufacturer: CCTC(三环); AddInBom: yes; ModelId: 624118aa3cc7497086c383c2d72e0852; ModelName: C0603_L1.6-W0.8-H0.8; ModelTransform: 62.992,31.496,0,0,0,0,0,0,0; Tolerance: ±10%; Voltage Rating: 50V; Temperature Coefficient: X7R
C16 C17 = 0603X105K100NT: Capacitance:1uF Tolerance:±10% Tolerance:±10% Voltage Rating:10V Temperature Coefficient:X5R; Manufacturer: FH(风华); AddInBom: yes; ModelId: 624118aa3cc7497086c383c2d72e0852; ModelName: C0603_L1.6-W0.8-H0.8; ModelTransform: 62.992,31.496,0,0,0,0,0,0,0; Tolerance: ±10%; Voltage Rating: 10V; Temperature Coefficient: X5R
C18 = CC0603KRX7R6BB104: Capacitance:100nF Tolerance:±10% Tolerance:±10% Voltage Rating:10V Temperature Coefficient:X7R; Manufacturer: YAGEO(国巨); Value: 100nF; AddInBom: yes; ModelId: 624118aa3cc7497086c383c2d72e0852; ModelName: C0603_L1.6-W0.8-H0.8; ModelTransform: 62.992,31.496,0,0,0,0,0,0,0; Tolerance: ±10%; Voltage Rating: 10V; Temperature Coefficient: X7R
C26 = CL10B102KB8NNNC: Capacitance:1nF Tolerance:±10% Tolerance:±10% Voltage Rating:50V Temperature Coefficient:X7R; Manufacturer: SAMSUNG(三星); AddInBom: yes; ModelId: 624118aa3cc7497086c383c2d72e0852; ModelName: C0603_L1.6-W0.8-H0.8; ModelTransform: 62.992,31.496,0,0,0,0,0,0,0; Tolerance: ±10%; Voltage Rating: 50V; Temperature Coefficient: X7R
C27 = FCC0603B103K500CT: Capacitance:10nF Tolerance:±10% Tolerance:±10% Voltage Rating:50V Temperature Coefficient:X7R; Manufacturer: FOJAN(富捷); AddInBom: yes; ModelId: 624118aa3cc7497086c383c2d72e0852; ModelName: C0603_L1.6-W0.8-H0.8; ModelTransform: 62.992,31.496,0,0,0,0,0,0,0; Tolerance: ±10%; Voltage Rating: 50V; Temperature Coefficient: X7R
C30 C31 = CL10A106KP8NNNC: Capacitance:10uF Tolerance:±10% Tolerance:±10% Voltage Rating:10V Temperature Coefficient:X5R; Manufacturer: SAMSUNG(三星); AddInBom: yes; ModelId: 624118aa3cc7497086c383c2d72e0852; ModelName: C0603_L1.6-W0.8-H0.8; ModelTransform: 62.992,31.496,0,0,0,0,0,0,0; Tolerance: ±10%; Voltage Rating: 10V; Temperature Coefficient: X5R
C32 C33 = CL21A475KBQNNNE: Capacitance:4.7uF Tolerance:±10% Tolerance:±10% Voltage Rating:50V Temperature Coefficient:X5R; Manufacturer: SAMSUNG(三星); AddInBom: yes; ModelId: 8c88e81f49c6409b980720ec8953afb6; ModelName: C0805_L2.0-W1.3-H1.3; ModelTransform: 78.74,51.181,0,0,0,0,0,0.0005,0; Tolerance: ±10%; Voltage Rating: 50V; Temperature Coefficient: X5R
C34 C35 C37 = GRM188R71H104KA93D: Capacitance:100nF Tolerance:±10% Tolerance:±10% Voltage Rating:50V Temperature Coefficient:X7R; Manufacturer: muRata(村田); AddInBom: yes; ModelId: 624118aa3cc7497086c383c2d72e0852; ModelName: C0603_L1.6-W0.8-H0.8; ModelTransform: 62.992,31.496,0,0,0,0,0,0,0; Tolerance: ±10%; Voltage Rating: 50V; Temperature Coefficient: X7R
C36 = C1608X5R1A685KT000E: Capacitance:6.8uF Tolerance:±10% Tolerance:±10% Voltage Rating:10V Temperature Coefficient:X5R; Manufacturer: TDK; AddInBom: yes; ModelId: 624118aa3cc7497086c383c2d72e0852; ModelName: C0603_L1.6-W0.8-H0.8; ModelTransform: 62.992,31.496,0,0,0,0,0,0,0; Tolerance: ±10%; Voltage Rating: 10V; Temperature Coefficient: X5R
CH340K CH340K-2 = CH340K: Applications Function:USB to serial Protocol:USB 2.0 Number of Channels:- Voltage - Supply:3.3V；5V Voltage - Supply:3.3V；5V Data Rate:2Mbps Operating Temperature:-20℃~+70℃ Operating Temperature:-20℃~+70℃; Manufacturer: WCH(南京沁恒); AddInBom: yes; ModelId: 2c41776ad5ce43918c42a52f44d2c6ae; ModelName: ESOP-10_L4.9-W3.9-H1.4-P1.00-LS6.2-BL-EP; ModelTransform: 192.913,242.1255,0,0,0,0,0,0,0; Protocol: USB 2.0; Data Rate: 2Mbps
E-INK = FPC-05F-24PH20: Locking Feature:Hinged Lid Contact Type:Surface Mount Number of Contacts:24P Pitch:0.5mm Mounting Type:Bottom Contact FFC, FCB Thickness:0.3mm FFC, FCB Thickness:0.3mm Height Above Board:2mm Contact Material:Phosphor Bronze Contact Plating:Tin Operating T; Manufacturer: XUNPU(讯普); AddInBom: yes; ModelId: 39b6f87f694b4e5ca6c0d21fa6e92623; ModelTransform: 645.668,201.5744,0,0,0,0,-0.003,-47.244,0; Number of Contacts: 24P; Pitch: 0.5mm; FFC, FCB Thickness: 0.3mm; Rated Voltage (Max): 50V; Current Rating (Max): 500mA
ENCODER = AFA01-S04FCA-00: Pitch:1mm Number of Contacts:4P Locking Feature:Clamshell FFC, FCB Thickness:0.3mm FFC, FCB Thickness:0.3mm Contact Type:Bottom Contact Mounting Type:Surface Mount Height Above Board:2mm Operating Temperature Range:-20℃~+85℃ Operating Temperature Range:-2; Manufacturer: JS(钜硕电子); AddInBom: yes; ModelId: a76b58d5d9dd4bde80414d127e275cec; ModelTransform: 389.763,234.2515,0,0,0,0,0,-70.197,0; Pitch: 1mm; Number of Contacts: 4P; FFC, FCB Thickness: 0.3mm
ESP_BOOT ESP_RST MASKROM RST_CMPT = HX 3x6x2.5A-2.5N: Circuit:SPST Actuator Style:Square Button Operating Force:2.5N Mounting Type:Surface Mount,Vertical Length:6mm Width:3.6mm Switch Height:2.5mm with Bracket:Without Bracket Contact Current:50mA Voltage Rating:12V Actuator/Cap Color:White With Lamp:No IP Ra; Manufacturer: hanxia(韩下); Symbol: HX TS-1101-C-W; AddInBom: yes; ModelId: 5e1db8552bd8464f811de570386c8572; ModelTransform: 314.96,141.732,0,0,0,0,0,0,0; Circuit: SPST; Operating Force: 2.5N; Switch Height: 2.5mm; Contact Current: 50mA; Voltage Rating: 12V; Actuator/Cap Color: White; With Lamp: No; Life: 30,000 Cycles
FILT = HX1188NL_C6176011: Turns Ratio:1:1 Operating Temperature:-40℃~+85℃ Operating Temperature:-40℃~+85℃; Manufacturer: PULSE(普思); AddInBom: yes; ModelId: ba9fe0a190224b589d94aba9370ff8f7; ModelTransform: 499.999,370.078,0,0,0,0,0,0,0; Turns Ratio: 1:1
L1 = ANR4012T1R0N: Inductance:1uH Tolerance:±30% Tolerance:±30% Current Rating:2.5A Current - Saturation(Isat):3.2A Type:Magnetic Shielded Inductor; Manufacturer: APV(爱普微); AddInBom: yes; Tolerance: ±30%; Current Rating: 2.5A; Current - Saturation(Isat): 3.2A
L2 = MPZ2012S601AT000: Impedance @ Frequency:600Ω@100MHz Tolerance:±25% Tolerance:±25% DC Resistance(DCR):100mΩ Current Rating:2A Number of Circuits:1 Operating Temperature:-55℃~+125℃ Operating Temperature:-55℃~+125℃; Manufacturer: TDK; AddInBom: yes; ModelId: b83c7c5430874b8eb2319a65d9433429; ModelName: R0805_L2.0-W1.3-H0.6; ModelTransform: 78.74,51.181,0,0,0,0,0,0.001,0; Tolerance: ±25%; DC Resistance(DCR): 100mΩ; Current Rating: 2A; Number of Circuits: 1
L3 = PSPMAA0605H-680M-IGF: Inductance:68uH Tolerance:±20% Tolerance:±20% Current Rating:1.5A Current - Saturation(Isat):2A DC Resistance(DCR):256mΩ Type:- Ratings:-; Manufacturer: PROD(谱罗德); AddInBom: yes; ModelId: 42305e89796f47b49312a685ea93d494; ModelName: IND-SMD_L7.1-W6.6-H5.0; ModelTransform: 275.59,259.88137,0,0,0,0,0,-0.551,0; Tolerance: ±20%; Current Rating: 1.5A; Current - Saturation(Isat): 2A; DC Resistance(DCR): 256mΩ
LED16 = WS2812B-2020: Wavelength:515.6nm；622.5nm；470.4nm Luminous Intensity:200mcd；160mcd；520mcd Fixed-Frequency Pwm Mode:- Data Transmission Rate:100KB/S Voltage - Supply:5V Voltage - Supply:5V Quiescent Current:- Lens Color:- ESD Withstand Voltage:- Installation method:op Vi; Manufacturer: worldsemi; AddInBom: yes; ModelId: 2073fdeeec114646a88cc45513eb03db; ModelName: LED-SMD_4P-L2.0-W2.0-H0.8-TL_WS2812B-2020; ModelTransform: 78.74,78.74,0,0,0,0,0.001,0.005,0; Voltage - Supply: 5V; Installation method: op View Mount
LEVEL_SHIFFTER-1 LEVEL_SHIFFTER-2 = 74AHCT1G125GV: Input type:- output type:Tri-State Voltage - Supply:4.5V~5.5V Voltage - Supply:4.5V~5.5V Number of Elements:1 Number of Bits per Element:1 Channel Type:Unidirectional Current - Output Low(IOL):8mA Current - Output High(IOH):8mA Logic Family:74AHCT Operati; Manufacturer: MDD(辰达半导体); AddInBom: yes; ModelId: 3168b22659ce4998ae232d44bb704e0a; ModelName: SOT-23-5_L2.9-W1.6-H1.1-LS2.8-P0.95; ModelTransform: 118.60433,114.173,0,90,0,0,0.0005,0.0005,0; Number of Elements: 1; Current - Output Low(IOL): 8mA; Logic Family: 74AHCT; Quiescent Current: 40uA; Propagation Delay: 1ns@4.5V
M1 = LD_MAX98357_Module: AddInBom: yes
P-SCL P-SDA = FRC0603F2201TS: Type:Thick Film Resistor Resistance:2.2kΩ Tolerance:±1% Tolerance:±1% Power(Watts):100mW Voltage-Supply(Max):75V Temperature Coefficient:±100ppm/℃ Temperature Coefficient:±100ppm/℃ Operating Temperature:-55℃~+155℃ Operating Temperature:-55℃~+155℃; Manufacturer: FOJAN(富捷); AddInBom: yes; ModelId: 112863783b5b41f1b5254f87eedc7932; ModelTransform: 31.8897,63.7794,0,90,0,0,0,0,0; Tolerance: ±1%; Power(Watts): 100mW; Voltage-Supply(Max): 75V
PHY = LAN8720AI-CP: Application Function:PHYtransceiver Number of Channels: Interface: Supply Voltage:1.6V~3.6V Supply Voltage:1.6V~3.6V Operating Temperature:0℃~+85℃ Operating Temperature:0℃~+85℃; Manufacturer: MICROCHIP(美国微芯); AddInBom: yes; ModelId: cc4c365db774488cad1074380ce98cec; ModelName: QFN-24_L4.0-W4.0-H0.9-P0.50; ModelTransform: 157.48,157.48,0,90,0,0,0,0,0
PORT-1-PORT-3 = YLED0805Y: Lamp Holder Type:- Illumination Color:Yellow Voltage - Forward(Vf):1.8V~2.4V Voltage - Forward(Vf):1.8V~2.4V Power(Watts):60mW Forward Current:20mA Wavelength - Dominant:584nm~596nm Wavelength - Dominant:584nm~596nm Peak Wavelength:598nm Peak Wavelength:5; Manufacturer: YONGYUTAI(永裕泰); AddInBom: yes; ModelId: 2a9c1b00fa874c3a8efdc4128cf62aaa; ModelTransform: 78.74,49.252,0,0,0,0,0,0,0; Illumination Color: Yellow; Power(Watts): 60mW; Forward Current: 20mA; Peak Wavelength: 598nm; Diode Configuration: Discrete Diode; Lens Color: Water Clear; Luminous Intensity: 210mcd; Viewing Angle: 120°
Q1 = SI1308EDL: Drain to Source Voltage:30V Current - Continuous Drain(Id):1.4A RDS(on):150mΩ@4.5V,0.5A Pd - Power Dissipation:360mW Gate Threshold Voltage (Vgs(th)):1.5V Gate Charge(Qg):2.6nC@4.5V Input Capacitance(Ciss):146pF@15V Reverse Transfer Capacitance (Crss@Vds); Manufacturer: TECH PUBLIC(台舟); Symbol: SI1308EDL_C7603347; AddInBom: yes; ModelId: 00b47c5ba4b548a981fce2870442aba0; ModelName: SOT-323-3_L2.0-W1.3-H1.0-LS2.1-P1.30; ModelTransform: 78.74,82.677,0,90,0,0,0.0005,0,0; Drain to Source Voltage: 30V; Current - Continuous Drain(Id): 1.4A; Pd - Power Dissipation: 360mW; Gate Threshold Voltage (Vgs(th)): 1.5V; Reverse Transfer Capacitance (Crss@Vds): 14.8pF@15V; Output Capacitance(Coss): 18.3pF
Q2 Q3 = BSS138_C27140738: Drain to Source Voltage:50V Current - Continuous Drain(Id):340mA RDS(on):1.5Ω@4.5V；1.29Ω@10V Pd - Power Dissipation:350mW Gate Threshold Voltage (Vgs(th)):1.6V@250uA Gate Charge(Qg):1.7nC@10V Input Capacitance(Ciss):32pF Reverse Transfer Capacitance (Crss; Manufacturer: HT(金誉); AddInBom: yes; ModelId: 4eed685bb9f4439b846746bc2193f3c0; ModelName: SOT-23-3L_L2.9-W1.6-H1.1-LS2.8-P0.95; ModelTransform: 114.173,110.236,0,90,0,0,0,0,0; Drain to Source Voltage: 50V; Current - Continuous Drain(Id): 340mA; Pd - Power Dissipation: 350mW; Input Capacitance(Ciss): 32pF; Reverse Transfer Capacitance (Crss@Vds): 0.9pF; Type: N-Channel; Output Capacitance(Coss): 7pF
Q4 Q5 = MMBT3904_C49435601: Manufacturer: Huixin(慧芯); AddInBom: yes; ModelId: e62cc26624594317b13e27ae0881521e; ModelTransform: 118.11,110.236,0,90,0,0,0,0,0
R1 R2 = 0603WAF5101T5E: Type:Thick Film Resistor Resistance:5.1kΩ Tolerance:±1% Tolerance:±1% Power(Watts):100mW Voltage-Supply(Max):75V Temperature Coefficient:±100ppm/℃ Temperature Coefficient:±100ppm/℃ Operating Temperature:-55℃~+155℃ Operating Temperature:-55℃~+155℃; Manufacturer: UNI-ROYAL(厚声); AddInBom: yes; ModelId: 112863783b5b41f1b5254f87eedc7932; ModelName: R0603; ModelTransform: 31.8897,63.7794,0,90,0,0,0,0,0; Tolerance: ±1%; Power(Watts): 100mW; Voltage-Supply(Max): 75V
R3-R6 = FRC0603F49R9TS: Type:Thick Film Resistor Resistance:49.9Ω Tolerance:±1% Tolerance:±1% Power(Watts):100mW Voltage-Supply(Max):75V Temperature Coefficient:±100ppm/℃ Temperature Coefficient:±100ppm/℃ Operating Temperature:-55℃~+155℃ Operating Temperature:-55℃~+155℃; Manufacturer: FOJAN(富捷); AddInBom: yes; ModelId: 112863783b5b41f1b5254f87eedc7932; ModelTransform: 31.8897,63.7794,0,90,0,0,0,0,0; Tolerance: ±1%; Power(Watts): 100mW; Voltage-Supply(Max): 75V
R7 = FRC0603F1212TS: Type:Thick Film Resistor Resistance:12.1kΩ Tolerance:±1% Tolerance:±1% Power(Watts):100mW Voltage-Supply(Max):75V Temperature Coefficient:±100ppm/℃ Temperature Coefficient:±100ppm/℃ Operating Temperature:-55℃~+155℃ Operating Temperature:-55℃~+155℃; Manufacturer: FOJAN(富捷); AddInBom: yes; ModelId: 112863783b5b41f1b5254f87eedc7932; ModelTransform: 31.8897,63.7794,0,90,0,0,0,0,0; Tolerance: ±1%; Power(Watts): 100mW; Voltage-Supply(Max): 75V
R8-R12 R26-R28 R54 = RC0603FR-0710KL_1: Type:Thick Film Resistors Resistance: Tolerance:±1% Tolerance:±1% Power(Watts): Overload Voltage (Max): Temperature Coefficient:±100ppm/℃ Temperature Coefficient:±100ppm/℃ Operating Temperature Range:-55℃~+155℃ Operating Temperature Range:-55℃~+155℃; Manufacturer: YAGEO(国巨); AddInBom: yes; ModelId: 112863783b5b41f1b5254f87eedc7932; ModelTransform: 31.8897,63.7794,0,90,0,0,0,0,0; Tolerance: ±1%
R13-R16 R21 = FRC0603F1002TS: Type:Thick Film Resistor Resistance:10kΩ Tolerance:±1% Tolerance:±1% Power(Watts):100mW Voltage-Supply(Max):75V Temperature Coefficient:±100ppm/℃ Temperature Coefficient:±100ppm/℃ Operating Temperature:-55℃~+155℃ Operating Temperature:-55℃~+155℃; Manufacturer: FOJAN(富捷); AddInBom: yes; ModelId: 112863783b5b41f1b5254f87eedc7932; ModelTransform: 31.8897,63.7794,0,90,0,0,0,0,0; Tolerance: ±1%; Power(Watts): 100mW; Voltage-Supply(Max): 75V
R17 R18 = Y1624260R000T9W: Type:Metal foil resistor Resistance:260Ω Tolerance:±0.01% Tolerance:±0.01% Power(Watts):200mW Temperature Coefficient:±0.2ppm/℃ Temperature Coefficient:±0.2ppm/℃ Operating Temperature:-55℃~+150℃ Operating Temperature:-55℃~+150℃; Manufacturer: VISHAY(威世); AddInBom: yes; ModelId: b83c7c5430874b8eb2319a65d9433429; ModelName: R0805_L2.0-W1.3-H0.6; ModelTransform: 78.74,51.181,0,0,0,0,0,-0.0005,0; Tolerance: ±0.01%; Power(Watts): 200mW
R19 = FRC0603F2701TS: Type:Thick Film Resistor Resistance:2.7kΩ Tolerance:±1% Tolerance:±1% Power(Watts):100mW Voltage-Supply(Max):75V Temperature Coefficient:±100ppm/℃ Temperature Coefficient:±100ppm/℃ Operating Temperature:-55℃~+155℃ Operating Temperature:-55℃~+155℃; Manufacturer: FOJAN(富捷); AddInBom: yes; ModelId: 112863783b5b41f1b5254f87eedc7932; ModelTransform: 31.8897,63.7794,0,90,0,0,0,0,0; Tolerance: ±1%; Power(Watts): 100mW; Voltage-Supply(Max): 75V
R20 = FRC0603F1000TS: Type:Thick Film Resistor Resistance:100Ω Tolerance:±1% Tolerance:±1% Power(Watts):100mW Voltage-Supply(Max):75V Temperature Coefficient:±100ppm/℃ Temperature Coefficient:±100ppm/℃ Operating Temperature:-55℃~+155℃ Operating Temperature:-55℃~+155℃; Manufacturer: FOJAN(富捷); AddInBom: yes; ModelId: 112863783b5b41f1b5254f87eedc7932; ModelTransform: 31.8897,63.7794,0,90,0,0,0,0,0; Tolerance: ±1%; Power(Watts): 100mW; Voltage-Supply(Max): 75V
R22 = FRC0603J103 TS: Type:Thick Film Resistor Resistance:10kΩ Tolerance:±5% Tolerance:±5% Power(Watts):100mW Voltage-Supply(Max):75V Temperature Coefficient:±100ppm/℃ Temperature Coefficient:±100ppm/℃ Operating Temperature:-55℃~+155℃ Operating Temperature:-55℃~+155℃; Manufacturer: FOJAN(富捷); AddInBom: yes; ModelId: 112863783b5b41f1b5254f87eedc7932; ModelTransform: 31.8897,63.7794,0,90,0,0,0,0,0; Tolerance: ±5%; Power(Watts): 100mW; Voltage-Supply(Max): 75V
R23 R29 = FRC0603J104 TS: Type:Thick Film Resistor Resistance:100kΩ Tolerance:±5% Tolerance:±5% Power(Watts):100mW Voltage-Supply(Max):75V Temperature Coefficient:±100ppm/℃ Temperature Coefficient:±100ppm/℃ Operating Temperature:-55℃~+155℃ Operating Temperature:-55℃~+155℃; Manufacturer: FOJAN(富捷); AddInBom: yes; ModelId: 112863783b5b41f1b5254f87eedc7932; ModelTransform: 31.8897,63.7794,0,90,0,0,0,0,0; Tolerance: ±5%; Power(Watts): 100mW; Voltage-Supply(Max): 75V
R24 = FRC0603J221 TS: Type:Thick Film Resistor Resistance:220Ω Tolerance:±5% Tolerance:±5% Power(Watts):100mW Voltage-Supply(Max):75V Temperature Coefficient:±100ppm/℃ Temperature Coefficient:±100ppm/℃ Operating Temperature:-55℃~+155℃ Operating Temperature:-55℃~+155℃; Manufacturer: FOJAN(富捷); AddInBom: yes; ModelId: 112863783b5b41f1b5254f87eedc7932; ModelTransform: 31.8897,63.7794,0,90,0,0,0,0,0; Tolerance: ±5%; Power(Watts): 100mW; Voltage-Supply(Max): 75V
R25 = 0603WAF2700T5E: Type:Thick Film Resistor Resistance:270Ω Tolerance:±1% Tolerance:±1% Power(Watts):100mW Voltage-Supply(Max):75V Temperature Coefficient:±100ppm/℃ Temperature Coefficient:±100ppm/℃ Operating Temperature:-55℃~+155℃ Operating Temperature:-55℃~+155℃; Manufacturer: UNI-ROYAL(厚声); AddInBom: yes; ModelId: 112863783b5b41f1b5254f87eedc7932; ModelTransform: 31.8897,63.7794,0,90,0,0,0,0,0; Tolerance: ±1%; Power(Watts): 100mW; Voltage-Supply(Max): 75V
R30 = FRC0603F2003TS: Type:Thick Film Resistor Resistance:200kΩ Tolerance:±1% Tolerance:±1% Power(Watts):100mW Voltage-Supply(Max):75V Temperature Coefficient:±100ppm/℃ Temperature Coefficient:±100ppm/℃ Operating Temperature:-55℃~+155℃ Operating Temperature:-55℃~+155℃; Manufacturer: FOJAN(富捷); AddInBom: yes; ModelId: 112863783b5b41f1b5254f87eedc7932; ModelTransform: 31.8897,63.7794,0,90,0,0,0,0,0; Tolerance: ±1%; Power(Watts): 100mW; Voltage-Supply(Max): 75V
R31 = 0603WAF4422T5E: Type:Thick Film Resistor Resistance:44.2kΩ Tolerance:±1% Tolerance:±1% Power(Watts):100mW Voltage-Supply(Max):75V Temperature Coefficient:±100ppm/℃ Temperature Coefficient:±100ppm/℃ Operating Temperature:-55℃~+155℃ Operating Temperature:-55℃~+155℃; Manufacturer: UNI-ROYAL(厚声); AddInBom: yes; ModelId: 112863783b5b41f1b5254f87eedc7932; ModelTransform: 31.8897,63.7794,0,90,0,0,0,0,0; Tolerance: ±1%; Power(Watts): 100mW; Voltage-Supply(Max): 75V
R32 = FRC0402P000 TS: Type:Thick Film Resistor Resistance:0Ω Tolerance:±5% Tolerance:±5% Power(Watts):62.5mW Voltage-Supply(Max):50V Operating Temperature:-55℃~+155℃ Operating Temperature:-55℃~+155℃; Manufacturer: FOJAN(富捷); AddInBom: yes; ModelId: efdecb7dae4442949d28eecaf748420f; ModelName: R0402_L1.0-W0.5-H0.4; ModelTransform: 39.37,19.685,0,0,0,0,0,0,0; Tolerance: ±5%; Power(Watts): 62.5mW; Voltage-Supply(Max): 50V
R33-R36 = 0603WAF750JT5E: Type:Thick Film Resistor Resistance:75Ω Tolerance:±1% Tolerance:±1% Power(Watts):100mW Voltage-Supply(Max):75V Temperature Coefficient:±100ppm/℃ Temperature Coefficient:±100ppm/℃ Operating Temperature:-55℃~+155℃ Operating Temperature:-55℃~+155℃; Manufacturer: UNI-ROYAL(厚声); AddInBom: yes; ModelId: 112863783b5b41f1b5254f87eedc7932; ModelTransform: 31.8897,63.7794,0,90,0,0,0,0,0; Tolerance: ±1%; Power(Watts): 100mW; Voltage-Supply(Max): 75V
R37-R40 R42-R44 R46-R53 R55-R61 = FRC0603J220 TS: Type:Thick Film Resistor Resistance:22Ω Tolerance:±5% Tolerance:±5% Power(Watts):100mW Voltage-Supply(Max):75V Temperature Coefficient:±100ppm/℃ Temperature Coefficient:±100ppm/℃ Operating Temperature:-55℃~+155℃ Operating Temperature:-55℃~+155℃; Manufacturer: FOJAN(富捷); AddInBom: yes; ModelId: 112863783b5b41f1b5254f87eedc7932; ModelTransform: 31.8897,63.7794,0,90,0,0,0,0,0; Tolerance: ±5%; Power(Watts): 100mW; Voltage-Supply(Max): 75V
R41 = FRC0603F1501TS: Type:Thick Film Resistor Resistance:1.5kΩ Tolerance:±1% Tolerance:±1% Power(Watts):100mW Voltage-Supply(Max):75V Temperature Coefficient:±100ppm/℃ Temperature Coefficient:±100ppm/℃ Operating Temperature:-55℃~+155℃ Operating Temperature:-55℃~+155℃; Manufacturer: FOJAN(富捷); AddInBom: yes; ModelId: 112863783b5b41f1b5254f87eedc7932; ModelTransform: 31.8897,63.7794,0,90,0,0,0,0,0; Tolerance: ±1%; Power(Watts): 100mW; Voltage-Supply(Max): 75V
R45 = FRC0603J104 TS: Type:Thick Film Resistor Resistance:100kΩ Tolerance:±5% Tolerance:±5% Power(Watts):100mW Voltage-Supply(Max):75V Temperature Coefficient:±100ppm/℃ Temperature Coefficient:±100ppm/℃ Operating Temperature:-55℃~+155℃ Operating Temperature:-55℃~+155℃; Manufacturer: FOJAN(富捷); AddInBom: yes; ModelId: 112863783b5b41f1b5254f87eedc7932; ModelTransform: 31.8897,63.7794,0,90,0,0,0,0,0; Value: 100kΩ; Tolerance: ±5%; Power(Watts): 100mW; Voltage-Supply(Max): 75V
R-RX1 R-RX2 R-TX1 R-TX2 = 0603WAF1001T5E: Type:Thick Film Resistor Resistance:1kΩ Tolerance:±1% Tolerance:±1% Power(Watts):100mW Voltage-Supply(Max):75V Temperature Coefficient:±100ppm/℃ Temperature Coefficient:±100ppm/℃ Operating Temperature:-55℃~+155℃ Operating Temperature:-55℃~+155℃; Manufacturer: UNI-ROYAL(厚声); AddInBom: yes; ModelId: 112863783b5b41f1b5254f87eedc7932; ModelName: R0603; ModelTransform: 31.8897,63.7794,0,90,0,0,0,0,0; Tolerance: ±1%; Power(Watts): 100mW; Voltage-Supply(Max): 75V
REG = Connector_Conn_01x04_Male: AddInBom: yes; Value: TLV62569_3v3BuckConverterBreakout
RJ45 = R-RJ45R08P-C000: Connector Type:RJ45 Jack Mounting Type:Right Angle Number of Ports:1 LED:With LED Shielding:Shielded Ratings:- PoE:- Supplementary Features:Harpoon Contact (Plastic) Contact Material:- Contact Plating:- Operating Temperature:0℃~+70℃ Operating Temperature:; Manufacturer: Ckmtw(灿科盟); AddInBom: yes; ModelId: a69862e215bb4bedbb366f2c7db375f4; ModelTransform: 651.9672,629.91996,0,0,0,0,0,-126.771,-137.795; Number of Ports: 1
RTC = PCF2129T/2,518: Interface:I2C；SPI Voltage - Supply:1.8V~4.2V Voltage - Supply:1.8V~4.2V Current - Supply:700nA crystal oscillator:Built-in Alarm Output:Yes Operating Temperature:-40℃~+85℃ Operating Temperature:-40℃~+85℃ Quiescent Current(Iq):0.7uA; Manufacturer: NXP(恩智浦); AddInBom: yes; ModelId: 672b267703b547918289b7b880d5591b; ModelTransform: 405.511,405.511,0,0,0,0,0,0,0; Current - Supply: 700nA; Quiescent Current(Iq): 0.7uA
SBC = Radxa_rCore_RK3308: AddInBom: yes
SLOT1 = TF PUSH: Card Connection Mode:Push-Push Card Type:MicroSD Card (TF Card) Connector Type:Connector and Ejector Additional Card Detection Pins:No Supplementary Features:- Height Above Board:2mm Operating Temperature:-25℃~+90℃ Operating Temperature:-25℃~+90℃; Manufacturer: SHOU HAN(首韩); AddInBom: yes; ModelId: 38fe85a3a7ce4fbea215a86a16fcc74b; ModelTransform: 635.826,598.424,0,0,0,0,0.002,-82.441,-23.622; Additional Card Detection Pins: No
SLOT2 = TF-025: Manufacturer: Hanbo Electronic; AddInBom: yes
SPDIF = DLR2180: AddInBom: yes
TOF = FPC-05F-6PH20: Locking Feature:Hinged Lid Contact Type:Surface Mount Number of Contacts:6P Pitch:0.5mm Mounting Type:Bottom Contact FFC, FCB Thickness:0.3mm FFC, FCB Thickness:0.3mm Height Above Board:2mm Contact Material:Phosphor Bronze Contact Plating:Tin Operating Te; Manufacturer: XUNPU(讯普); AddInBom: yes; ModelId: 03841dd804654387977a90b8a5524c4d; ModelTransform: 291.338,220.472,0,0,0,0,-0.001,-45.276,0; Number of Contacts: 6P; Pitch: 0.5mm; FFC, FCB Thickness: 0.3mm; Rated Voltage (Max): 50V; Current Rating (Max): 500mA
Top_PCB = ZX-1.0FPC-2H-QFX17P: Locking Feature:Hinged Lid Contact Type:Bottom Contact Number of Contacts:17P Pitch:1mm Mounting Type:Surface Mount, Right Angle FFC, FCB Thickness:0.3mm FFC, FCB Thickness:0.3mm Height Above Board:2mm Contact Material:Copper alloy Contact Plating:Tin Ope; Manufacturer: Megastar(兆星); AddInBom: yes; ModelId: 937d878fdcf348138d9ffcb84035bd35; ModelTransform: 862.5967,236.22,0,0,0,0,-5.04,-44.941,0; Number of Contacts: 17P; Pitch: 1mm; FFC, FCB Thickness: 0.3mm; Rated Voltage (Max): 50V
U21-U23 = MBR0530_C5204746: Diode Configuration:Independent Voltage - Forward(Vf@If):500mV@500mA Voltage - DC Reverse(Vr):30V Current - Rectified:500mA Reverse Leakage Current (Ir):130uA Non-Repetitive Peak Forward Surge Current:5.5A; Manufacturer: TWGMC(迪嘉); AddInBom: yes; ModelId: 5a61cd31046d4447ba73169a45a0935b; ModelTransform: 151.575,66.929,0,0,0,0,0,0,0; Voltage - DC Reverse(Vr): 30V; Current - Rectified: 500mA; Reverse Leakage Current (Ir): 130uA; Non-Repetitive Peak Forward Surge Current: 5.5A
U24 = ESP32-WROOM-32U-N4_C328062: Utilized IC / Part:ESP32-DOWD Wireless Standard:Bluetooth4.2 Interface Type:I2C；GPIO；UART；DAC；SPI；PWM；SDIO；ADC；CAN Frequency:2.4GHz Output Power:20.5dBm Output Power:20.5dBm Voltage - Supply:3V~3.6V Voltage - Supply:3V~3.6V Sensitivity:-97dBm Sensitivity:; Manufacturer: ESPRESSIF(乐鑫); AddInBom: yes; ModelId: 750d79ab7ed74c39bca65e32d20b18a1; ModelName: WIFIM-SMD_38P-L19.2-W18.0-H3.2-P1.27; ModelTransform: 755.904,708.66,0,0,0,0,25.59,-0.002,0; Sensitivity: -97dBm
USB-C2 = UC.01.51-11-0017,typec: AddInBom: yes; ModelId: e0a9d83f704144a48dae8635b7823cc8; ModelTransform: 351.9678,266.1412,0,0,0,0,0,-31.493,-31.496
USB_HOST = UE27AC54100: Connector Type:Type-A Protocol Standard:USB 2.0 Gender:Female Mounting Type:Right Angle Number of Contacts:4P Number of Ports:1 Current Rating-Power:1A Voltage Rating:30V Detection color:Black Operating Temperature:-40℃~+85℃ Operating Temperature:-40℃~+85; Manufacturer: Amphenol; AddInBom: yes; ModelId: 79899d0fc9384fb7acd8a772ab763045; ModelName: USB-A-TH_4P-L14.4-W13.6-H7.0-S2.71; ModelTransform: 612.18618,535.432,0,0,0,0,0,-196.85,-137.795; Connector Type: Type-A; Protocol Standard: USB 2.0; Gender: Female; Number of Contacts: 4P; Number of Ports: 1; Current Rating-Power: 1A; Voltage Rating: 30V; Detection color: Black
USB_SWITCH = FE1.1S-BSOP28BCN: Applications Function:- USB Protocol:USB 2.0 Number of Channels:4 Voltage - Supply:4.5V~5.5V；3V~3.6V Voltage - Supply:4.5V~5.5V；3V~3.6V Operating Temperature:0℃~+70℃ Operating Temperature:0℃~+70℃ Supply Current (Iq):800uA; Manufacturer: TERMINUS; Symbol: FE1.1S; AddInBom: yes; ModelId: dfa917eaf3b54f2088318683fc7b46fb; ModelTransform: 390.1567,235.826,0,0,0,0,0,0,0; USB Protocol: USB 2.0; Number of Channels: 4; Supply Current (Iq): 800uA
X2 = SX5B25.000F2020F30: Type:Crystal Oscillator Frequency:25MHz Normal temperature Frequency Tolerance:±20ppm Normal temperature Frequency Tolerance:±20ppm Load Capacitance:20pF Frequency Stability:±30ppm Frequency Stability:±30ppm Equivalent Series Resistance(ESR):30Ω Operating; Manufacturer: SCTF(星通时频); AddInBom: yes; ModelId: 701e1f32ae8c4344bf4037d0fc939a81; ModelTransform: 196.85,125.984,0,0,0,0,0,0,0; Normal temperature Frequency Tolerance: ±20ppm; Load Capacitance: 20pF; Frequency Stability: ±30ppm; Equivalent Series Resistance(ESR): 30Ω
X3 = X322512MSB4SI: Type:Crystal Oscillator Frequency:12MHz Normal temperature Frequency Tolerance:±10ppm Normal temperature Frequency Tolerance:±10ppm Load Capacitance:20pF Frequency Stability:±20ppm Frequency Stability:±20ppm Operating Temperature:-40℃~+85℃ Operating Tempe; Manufacturer: YXC(扬兴晶振); AddInBom: yes; ModelId: a2b47bc5d32f4dfd996128e047b549a0; ModelTransform: 125.984,98.425,0,0,0,0,0,0,0; Normal temperature Frequency Tolerance: ±10ppm; Load Capacitance: 20pF; Frequency Stability: ±20ppm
